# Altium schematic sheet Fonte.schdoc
size 219 x 142 mm
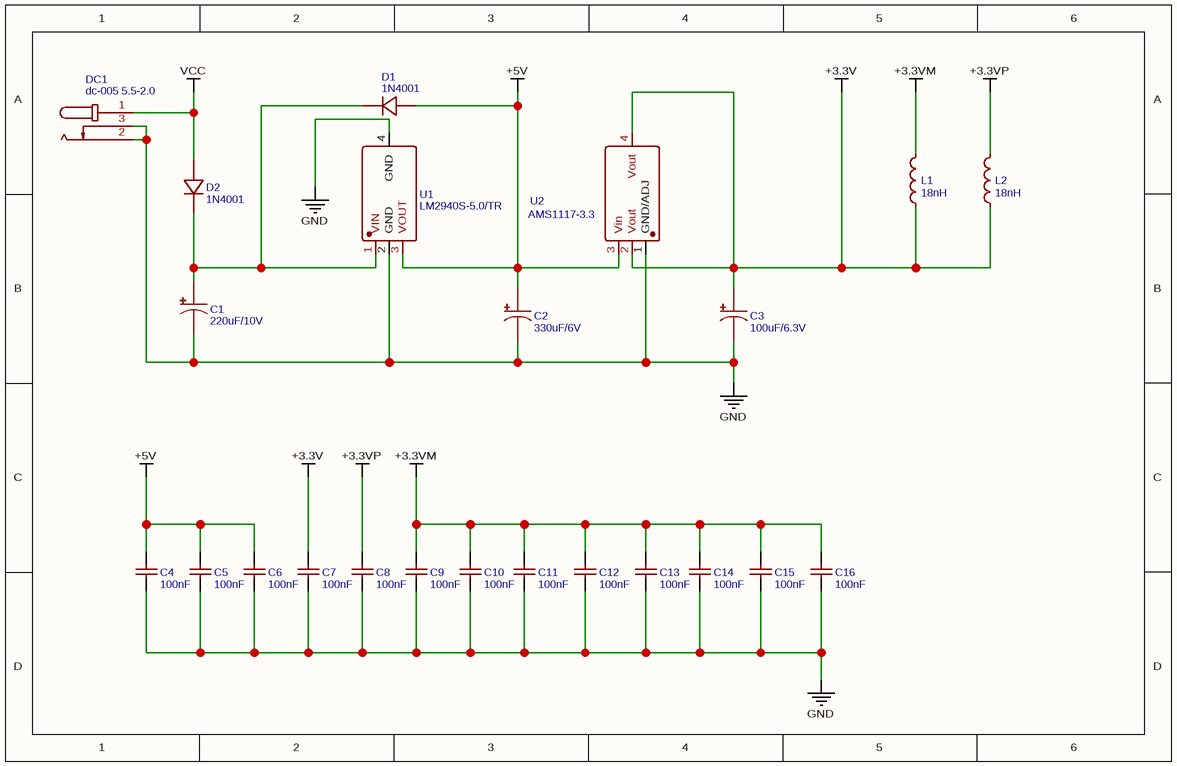
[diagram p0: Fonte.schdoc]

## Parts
C1  220uF/10V  [CAP-SMD_BD8.0-L8.5-W8.5-FD]
C2  330uF/6V  [CAP-SMD_BD6.3-L6.6-W6.6-FD]
C3  100uF/6.3V  [CAP-SMD_BD5.0-L5.3-W5.3-FD]
C4  100nF  [C0402]
C5  100nF  [C0402]
C6  100nF  [C0402]
C7  100nF  [C0402]
C8  100nF  [C0402]
C9  100nF  [C0402]
C10  100nF  [C0402]
C11  100nF  [C0402]
C12  100nF  [C0402]
C13  100nF  [C0402]
C14  100nF  [C0402]
C15  100nF  [C0402]
C16  100nF  [C0402]
D1  1N4001  [SMA_L4.4-W2.6-LS5.0-RD]
D2  1N4001  [SMA_L4.4-W2.6-LS5.0-RD]
DC1  dc-005 5.5-2.0  [DC-IN-TH_DC005]
L1  18nH  [L0402]
L2  18nH  [L0402]
U1  LM2940S-5.0/TR  [TO-263-3_L8.6-W10.2-P2.54-LS14.4-BR]
U2  AMS1117-3.3  [SOT-223-3_L6.5-W3.4-P2.30-LS7.0-BR]

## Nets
+3.3V: C3.1 C7.2 L1.1 L2.1 U2.2(Vout) U2.4(Vout)
+3.3VM: C9.2 C10.2 C11.2 C12.2 C13.2 C14.2 C15.2 C16.2 L1.2
+3.3VP: C8.2 L2.2
+5V: C2.1 C4.2 C5.2 C6.2 D1.2(A) U1.3(VOUT) U2.3(Vin)
GND: C1.2 C2.2 C3.2 C4.1 C5.1 C6.1 C7.1 C8.1 C9.1 C10.1 C11.1 C12.1 C13.1 C14.1 C15.1 C16.1 DC1.2 DC1.3 U1.2(GND) U1.4(GND) U2.1(GND/ADJ)
VCC: D2.2(A) DC1.1
NetC1_1: C1.1 D1.1(K) D2.1(K) U1.1(VIN)

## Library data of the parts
C1 = 220uF/10V: BOM_Manufacturer: PANASONIC; BOM_Manufacturer Part: EEHZC1E221V; nameAlias: Capacitance; Contributor: LCSC; Package Display: No
C2 = 330uF/6V: BOM_Manufacturer: HONOR; BOM_Manufacturer Part: RVT1A221M0607; nameAlias: Capacitance; Package Display: No
C3 = 100uF/6.3V: BOM_Manufacturer: PANASONIC; BOM_Manufacturer Part: EEEFT1C680AR; nameAlias: Capacitance; Contributor: LCSC; Package Display: No
C4-C16 = 100nF: BOM_Manufacturer Part: CL05B104KO5NNNC; BOM_Manufacturer: SAMSUNG; nameAlias: Capacitance; SMT Type: Basic; BOM_Paste Type: base
D1 D2 = 1N4001: BOM_Manufacturer: TWGMC; Contributor: LCSC; Package Display: No
DC1 = dc-005 5.5-2.0: BOM_Manufacturer: Shenzhen Cankemeng; Contributor: LCSC; BOM_Assembly Type: manualWeld; BOM_Paste Type: expand; Package Display: No
L1 L2 = 18nH: BOM_Manufacturer: Sunlord; BOM_Manufacturer Part: SDCL1005C18NJTDF; nameAlias: Inductance; SMT Type: Basic; BOM_Paste Type: base
U1 = LM2940S-5.0/TR: BOM_Manufacturer: HGSEMI; Contributor: LCSC; Package Display: No
U2 = AMS1117-3.3: BOM_Manufacturer: AMS; sourceId: dwIGgezVh; SMT Type: Basic; BOM_Assembly Type: smtWeld; BOM_Paste Type: base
